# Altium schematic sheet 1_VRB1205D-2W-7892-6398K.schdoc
size 289 x 200 mm; Name: default297x210; Symbol: default297x210; Device: default297x210; Size: "A4"; Id: /; File: EV_CMP7892_08B_03; Sheet: /
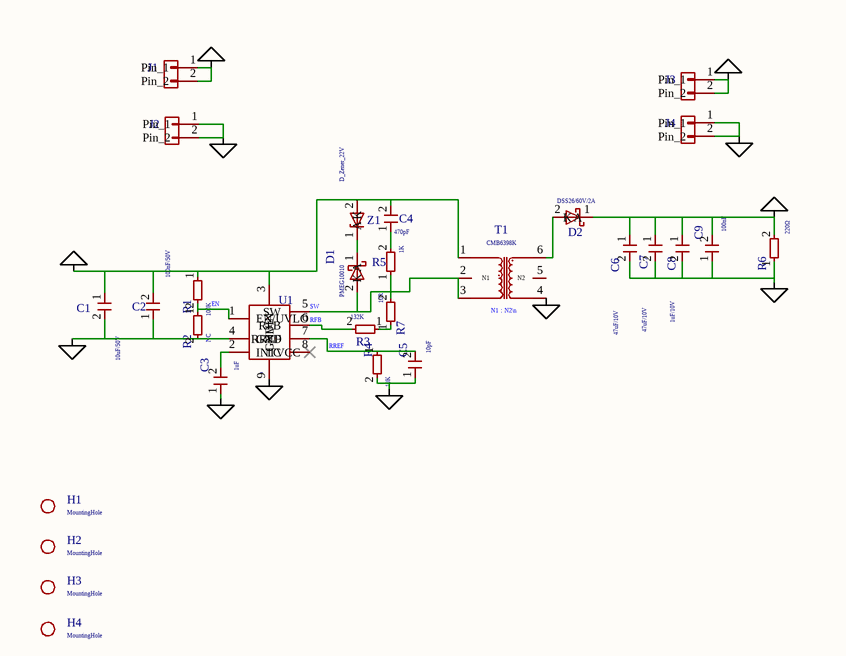
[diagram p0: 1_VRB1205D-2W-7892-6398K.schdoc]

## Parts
C1  value 10uF/50V  [MYLibrary:C0805]  (hidden comment: MY_C)
C2  value 100nF/50V  [MYLibrary:C0603]  (hidden comment: MY_C)
C3  value 1uF  [MYLibrary:C0603]  (hidden comment: MY_C)
C4  value 470pF  [MYLibrary:C0603]  (hidden comment: My_library_C)
C5  value 10pF  [MYLibrary:C0603]  (hidden comment: My_library_C)
C6  value 47uF/10V  [MYLibrary:C0805]  (hidden comment: MY_C)
C7  value 47uF/10V  [MYLibrary:C0805]  (hidden comment: MY_C)
C8  value 1uF/10V  [MYLibrary:C0805]  (hidden comment: MY_C)
C9  value 100nF  [MYLibrary:C0603]  (hidden comment: MY_C)
D1  value PMEG10010  [MYLibrary:SOD-323-123-A]  (hidden comment: My library_DSS210)
D2  value DSS26/60V/2A  [MYLibrary:SOD-323-123-A]  (hidden comment: My library_DSS210)
H1  value MountingHole  [MountingHole:MountingHole_3.2mm_M3]  (hidden comment: Mechanical_MountingHole)
H2  value MountingHole  [MountingHole:MountingHole_3.2mm_M3]  (hidden comment: Mechanical_MountingHole)
H3  value MountingHole  [MountingHole:MountingHole_3.2mm_M3]  (hidden comment: Mechanical_MountingHole)
H4  value MountingHole  [MountingHole:MountingHole_3.2mm_M3]  (hidden comment: Mechanical_MountingHole)
J1  Connector_Generic_Conn_01x02  [Connector_PinHeader_2.54mm:PinHeader_1x02_P2.54mm_Vertical]  (value not drawn)
J2  Connector_Generic_Conn_01x02  [Connector_PinHeader_2.54mm:PinHeader_1x02_P2.54mm_Vertical]  (value not drawn)
J3  Connector_Generic_Conn_01x02  [Connector_PinHeader_2.54mm:PinHeader_1x02_P2.54mm_Vertical]  (value not drawn)
J4  Connector_Generic_Conn_01x02  [Connector_PinHeader_2.54mm:PinHeader_1x02_P2.54mm_Vertical]  (value not drawn)
R1  value 100K  [MYLibrary:R0603]  (hidden comment: Device_R_Small)
R2  value NC  [MYLibrary:R0603]  (hidden comment: Device_R_Small)
R3  value 132K  [MYLibrary:R0603]  (hidden comment: Device_R_Small)
R4  value 10K  [MYLibrary:R0603]  (hidden comment: Device_R_Small)
R5  value 1K  [MYLibrary:R0805]  (hidden comment: Device_R_Small)
R6  value 220Ω  [MYLibrary:R0805]  (hidden comment: Device_R_Small)
R7  value 10R  [MYLibrary:R0603]  (hidden comment: Device_R_Small)
T1  value CMB6398K  [MYLibrary:EP5_3+3_7.7x5.3]  (hidden comment: MYLibrary _CMT_3+3)
U1  value ~  [Package_SO:SOIC-8-1EP_3.9x4.9mm_P1.27mm_EP2.41x3.3mm_ThermalVias]  (hidden comment: MY_LT8302)
Z1  value D_Zener_22V  [MYLibrary:SOD-323-123-A]  (hidden comment: My library_D_Zener)

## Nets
POWER_+8V: C1.1 C2.2 C4.2 C6.1 C7.1 C8.1 C9.2 D2.1(K) J1.1(Pin_1) J1.2(Pin_2) J3.1(Pin_1) J3.2(Pin_2) R1.1 R6.2 T1.1 U1.3(VIN) Z1.2(A)
POWER_GND1: C1.2 C2.1 C3.1 C5.1 J2.1(Pin_1) J2.2(Pin_2) R2.2 R4.2 U1.4(GND) U1.9(GND)
POWER_GND2: C6.2 C7.2 C8.2 C9.1 J4.1(Pin_1) J4.2(Pin_2) R6.1 T1.4
EN: R1.2 R2.1 U1.1(EN/UVLO)
RFB: R3.2 U1.6(RFB)
RREF: C5.2 R4.1 U1.7(RREF)
SW: D1.2(A) R5.1 R7.2 T1.2 T1.3 U1.5(SW)
NetC3_2: C3.2 U1.2(INTVCC)
NetC4_1: C4.1 R5.2
NetD1_1: D1.1(K) Z1.1(K)
NetD2_2: D2.2(A) T1.6
NetR3_1: R3.1 R7.1

Not connected (* = marked no-connect by the designer): T1 5; U1 8(TC)*

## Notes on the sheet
- (near T1) N1：N2\n

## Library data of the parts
C1-C3 C6-C9 = MY_C: Users: REF**; ki_fp_filters: C_*; Add into BOM: yes
C4 C5 = My_library_C: Add into BOM: yes
D1 D2 = My library_DSS210: ki_fp_filters: TO-???* *_Diode_* *SingleDiode* D_*; Add into BOM: yes
H1-H4 = Mechanical_MountingHole: Users: REF**; ki_fp_filters: MountingHole*; Add into BOM: yes
J1-J4 = Connector_Generic_Conn_01x02: Users: REF**; ki_fp_filters: Connector*:*_1x??_*; Add into BOM: yes
R1-R4 R7 = Device_R_Small: Users: REF**; ki_fp_filters: R_*; Add into BOM: yes
R5 R6 = Device_R_Small: ki_fp_filters: R_*; Add into BOM: yes
T1 = MYLibrary _CMT_3+3: Symbol: CMT_3+3_1; Add into BOM: yes
U1 = MY_LT8302: Users: REF**; Add into BOM: yes
Z1 = My library_D_Zener: Add into BOM: yes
